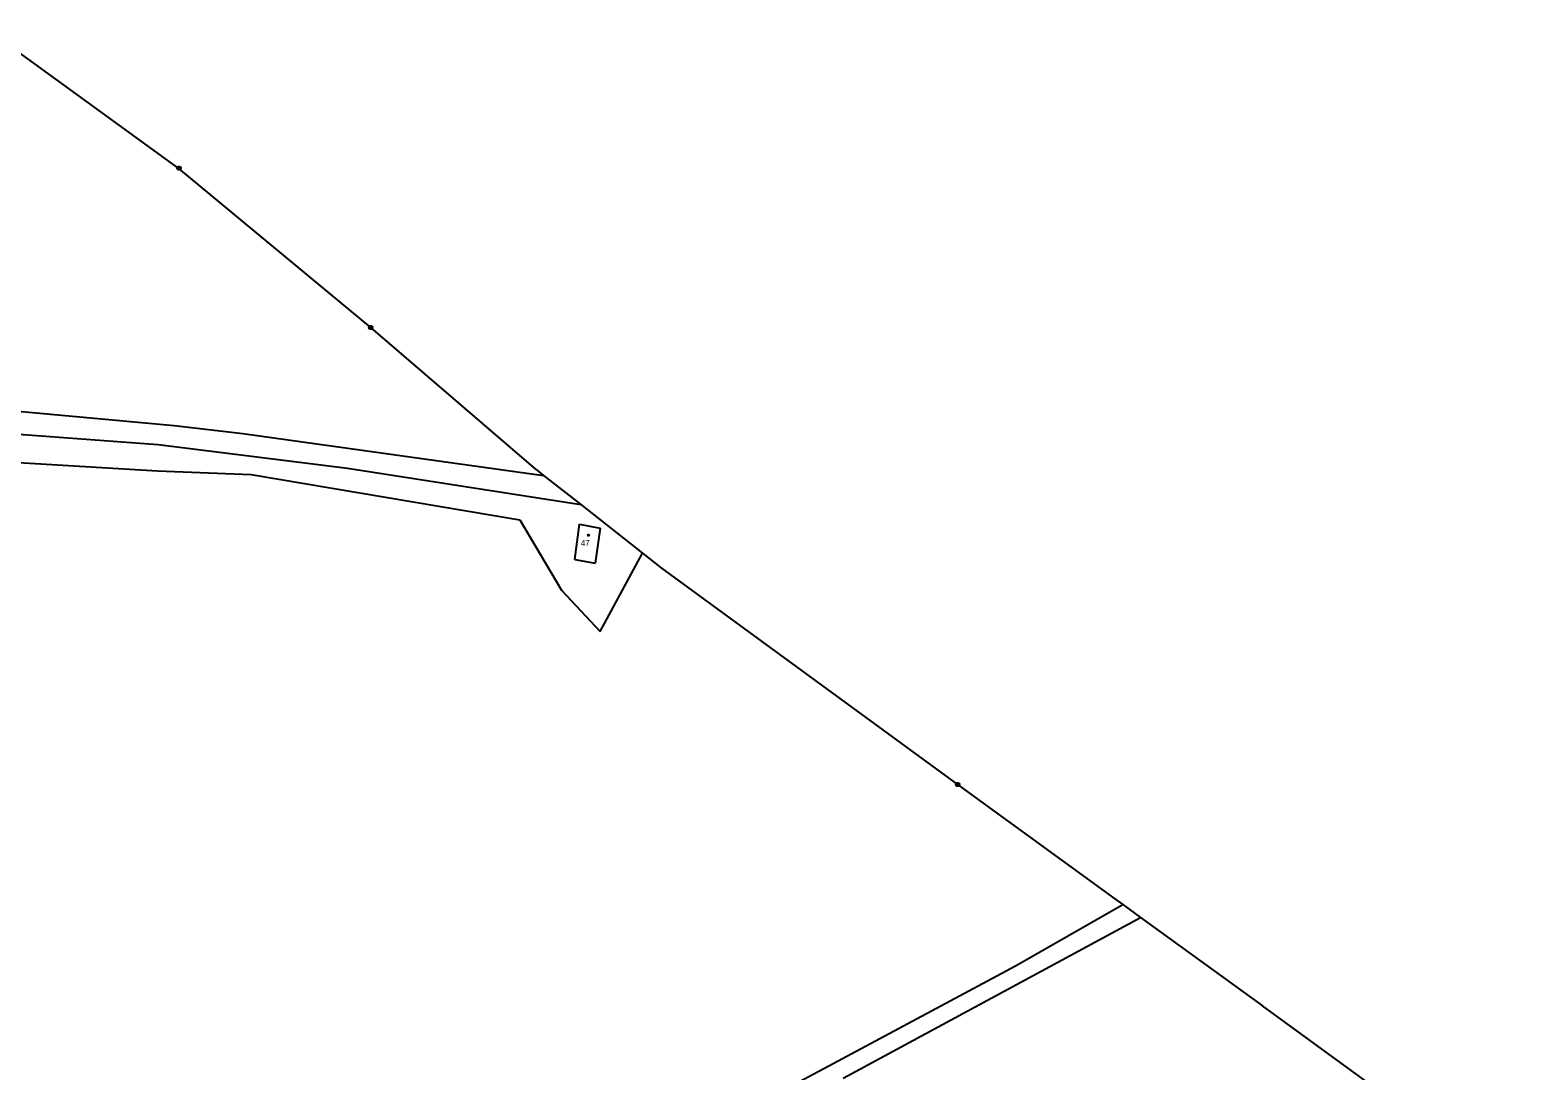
# Model space of a CAD drawing. Extents: x -780000 to -777378, y -1011169 to -1009297.
# Drawn here: x -777903.4 to -777476.3, y -1010425.5 to -1010130.8 of the extents above; entities that cross this region are included whole.
import ezdxf

# ---------------------------------------------------------------- set-up
doc = ezdxf.new("R2010")
doc.units = 0
for name, color, linetype in [('Default', 7, 'Continuous'), ('KN_HRANICE', 7, 'Continuous'), ('KN_KULTURY', 7, 'Continuous'), ('KN_PARCELY', 7, 'Continuous'), ('KN_VEDENI', 7, 'Continuous')]:
    doc.layers.add(name, color=color, linetype=linetype)

# ---------------------------------------------------------------- blocks, each defined once
blk = doc.blocks.new('NAHRADNI_SYMBOL')
at = {"layer": 'Default'}
blk.add_lwpolyline([(0.09, 0.15), (0.18, 0), (0.09, -0.15), (-0.09, -0.15), (-0.18, 0), (-0.09, 0.15), (0.09, 0.15)], dxfattribs=at)
blk = doc.blocks.new('105')
at = {"layer": 'Default'}
blk.add_line((-0.12, 0), (0.12, 0), dxfattribs=at)
blk.add_lwpolyline([(0.15, 0.48), (0.4, 0.3), (0.5, 0.01), (0.4, -0.28), (0.15, -0.46), (-0.16, -0.46), (-0.41, -0.28), (-0.51, 0.01), (-0.41, 0.3), (-0.16, 0.48), (0.15, 0.48)], dxfattribs=at)

msp = doc.modelspace()

# ---------------------------------------------------------------- linework, layer by layer
at = {"layer": 'KN_HRANICE'}
for p, q in [((-777861.25, -1010169.9), (-777915.32, -1010130.76)), ((-777806.93, -1010215.01), (-777861.25, -1010169.9)), ((-777760.11, -1010255.16), (-777806.93, -1010215.01)), ((-777916.19, -1010237.79), (-777862.6, -1010242.68)), ((-777862.6, -1010242.68), (-777843.18, -1010245)), ((-777843.18, -1010245), (-777757.95, -1010256.86)), ((-777987.12, -1010248.38), (-777867.3, -1010255.54)), ((-777867.3, -1010255.54), (-777840.84, -1010256.64)), ((-777840.84, -1010256.64), (-777764.7, -1010269.46)), ((-777760.11, -1010255.16), (-777757.95, -1010256.86)), ((-777757.95, -1010256.86), (-777747.45, -1010265.13)), ((-777747.45, -1010265.13), (-777729.99, -1010278.87)), ((-777764.7, -1010269.46), (-777752.89, -1010289.37)), ((-777749.15, -1010280.66), (-777747.78, -1010270.64)), ((-777747.78, -1010270.64), (-777741.9, -1010271.79)), ((-777741.9, -1010271.79), (-777743.37, -1010281.68)), ((-777741.89, -1010301.03), (-777729.99, -1010278.87)), ((-777729.99, -1010278.87), (-777724.59, -1010283.12)), ((-777749.15, -1010280.66), (-777743.37, -1010281.68)), ((-777724.59, -1010283.12), (-777640.68, -1010344.39)), ((-777752.89, -1010289.37), (-777741.89, -1010301.03)), ((-777640.68, -1010344.39), (-777596.13, -1010376.74)), ((-777596.13, -1010376.74), (-777593.84, -1010378.4)), ((-777673.1, -1010427.53), (-777588.84, -1010382.03)), ((-777624.31, -1010395.77), (-777593.84, -1010378.4)), ((-777593.84, -1010378.4), (-777588.84, -1010382.03)), ((-777588.84, -1010382.03), (-777554.28, -1010407.13)), ((-777675.96, -1010423.46), (-777624.31, -1010395.77)), ((-777476.3, -1010463.75), (-777554.28, -1010407.13)), ((-777846.45, -1010513.92), (-777675.96, -1010423.46))]:
    msp.add_line(p, q, dxfattribs=at)
at = {"layer": 'KN_VEDENI'}
for p, q in [((-777985.16, -1010239.29), (-777867.19, -1010248.13)), ((-777867.19, -1010248.13), (-777813.48, -1010254.83)), ((-777813.48, -1010254.83), (-777747.45, -1010265.13))]:
    msp.add_line(p, q, dxfattribs=at)

# ---------------------------------------------------------------- block references
at = {"layer": 'KN_KULTURY'}
msp.add_blockref('NAHRADNI_SYMBOL', (-777745.22, -1010273.78), dxfattribs=at)
at = {"layer": 'KN_PARCELY'}
for p in [(-777861.25, -1010169.9), (-777806.93, -1010215.01), (-777640.68, -1010344.39)]:
    msp.add_blockref('105', p, dxfattribs=at)

# ---------------------------------------------------------------- texts
msp.add_text('47', height=1.7, dxfattribs=at).set_placement((-777747.44, -1010276.89))

doc.saveas('drawing.dxf')
